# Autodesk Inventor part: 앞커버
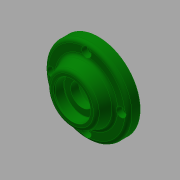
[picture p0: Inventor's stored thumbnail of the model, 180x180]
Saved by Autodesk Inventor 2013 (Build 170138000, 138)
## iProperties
Created: 2017-08
Part Number: 앞커버
Material: 알루미늄 6061
Document SubType Name: Modeling
Designer: mduedu
Density: 1 g/cm^3
Author: mduedu
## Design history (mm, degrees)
sketch "스케치1"
  geometry: C1 r 35 at (0, 0); 1 further point
  constraints: 1 centre point, 1 coincident
  dimensions: "d0" = 70 diameter of C1
extrude "돌출1" new body sketch "스케치1" distance "d1" = 10; taper "d2" = 0 deg
sketch "스케치2"
  geometry: C1 r 24 at (0, 0); 1 further point
  constraints: 1 centre point, 1 coincident
  dimensions: "d3" = 48 diameter of C1
node "작업 평면1"
sketch "스케치3"
  geometry: C1 r 20 at (0, 0); 1 further point
  constraints: 1 centre point, 1 coincident
  dimensions: "d5" = 40 diameter of C1
feature "로프트1" sketch "스케치3" dims "d6" = 0, "d7" = 90 deg, "d8" = 0, "d9" = 90 deg
sketch "스케치4"
  geometry: C1 r 24 at (0, 0) reference; 1 further point
extrude "돌출2" join sketch "스케치4" distance "d10" = 8; taper "d11" = 0 deg
hole "구멍1" diameter "d14" = 40; stored, may be unused: countersink angle "d18" = 90 deg, drill point angle "d20" = 0 deg; dims "d12" = 10, "d13" = 10, "d15" = 6, "d16" = 4, "d17" = 2, "d19" = 12
hole "구멍2" diameter "d23" = 34; stored, may be unused: countersink angle "d27" = 90 deg, drill point angle "d29" = 0 deg; dims "d21" = 10, "d22" = 10, "d24" = 6, "d25" = 4, "d26" = 2, "d28" = 3
hole "구멍3" diameter "d32" = 19; stored, may be unused: countersink angle "d36" = 90 deg, drill point angle "d38" = 0 deg; dims "d30" = 10, "d31" = 10, "d33" = 6, "d34" = 4, "d35" = 2, "d37" = 3
chamfer "모따기1" distance "d39" = 1; stored, may be unused: second distance "d40" = 2, angle "d41" = 45 deg
sketch "스케치5"
  geometry: C1 r 15 at (0, 0); 1 further point
  constraints: 1 centre point, 1 coincident
  dimensions: "d42" = 30 diameter of C1
extrude "돌출3" cut sketch "스케치5" distance "d43" = 8.3; taper "d44" = 0 deg
chamfer "모따기2" distance "d47" = 0.8; stored, may be unused: second distance "d48" = 2, angle "d49" = 30 deg
fillet "모깎기1" dims "d50" = 0.3
fillet "모깎기2" dims "d51" = 0.3
fillet "모깎기3" dims "d52" = 3
sketch "스케치6" dims "d53" = 58
  geometry: 6 further points
  constraints: 2 vertical alignment, 1 coincident, 7 other
  dimensions: "d56" = 360 deg dimension on point (0, 0) point (0, 29) (derived)
sketch "스케치9" dims "d85" = 58 (derived)
  geometry: 6 further points
  constraints: 1 coincident, 1 vertical alignment, 6 other
hole "구멍6" sketch "스케치9" at (-29, 0), (0, -29), (29, 0), (0, 29) diameter "d72" = 4.5; stored, may be unused: countersink angle "d76" = 90 deg, drill point angle "d78" = 0 deg; dims "d73" = 6, "d74" = 8, "d75" = 4.6, "d77" = 8
fillet "모깎기4" dims "d79" = 3
fillet "모깎기5" dims "d80" = 3
fillet "모깎기6" dims "d81" = 3
node "솔리드1"
other parameters: "d4" = 12
